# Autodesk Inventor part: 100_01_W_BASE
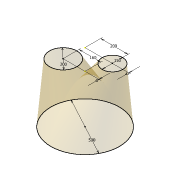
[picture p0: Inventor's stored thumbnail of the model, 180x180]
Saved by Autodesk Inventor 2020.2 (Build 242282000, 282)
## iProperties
Created: 2011-01
Part Number: 100_01_W_BASE
Document SubType Name: Modeling
Designer: F.Stasiak
Density: 1 g/cm^3
Material: Ogólny
Appearance: Domyślna
Catalog Web Link: www.expertbooks.eu
Company: Fabian Stasiak CAD Consulting
Category: Autodesk® Inventor® Tutorial Series
Author: F.Stasiak
Subject: Sheet Metal Design. Basic and Advanced techniques
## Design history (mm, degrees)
sketch "Szkic1"
  geometry: C1 r 250 at (0, 0); 1 further point
  constraints: 1 centre point, 1 coincident
  dimensions: "d0" = 500 diameter of C1
node "Płaszczyzna konstrukcyjna1"
sketch "Szkic2"
  geometry: C1 r 100 at (-160, 0); 1 further point
  constraints: 1 centre point
  dimensions: "d2" = 200 diameter of C1; "d3" = 160 distance of point (0, 0) C1.centre; "d4" = 0 vertical distance of point (0, 0) C1.centre
node "Płaszczyzna konstrukcyjna2"
sketch "Szkic3"
  geometry: C1 r 75 at (200, 0); 1 further point
  constraints: 1 centre point
  dimensions: "d6" = 150 diameter of C1; "d7" = 200 distance of point (0, 0) C1.centre; "d8" = 0 vertical distance of point (0, 0) C1.centre
feature "PowWyciągnięciaZłożonego1" dims "d9" = 0, "d10" = 90 deg, "d11" = 0, "d12" = 90 deg
feature "PowWyciągnięciaZłożonego2" dims "d13" = 0, "d14" = 90 deg, "d15" = 0, "d16" = 90 deg
  node "Krawędzie1"
feature "Utnij1"
feature "Utnij2"
node "Bryła1"
body "Srf1"
body "Srf2"
